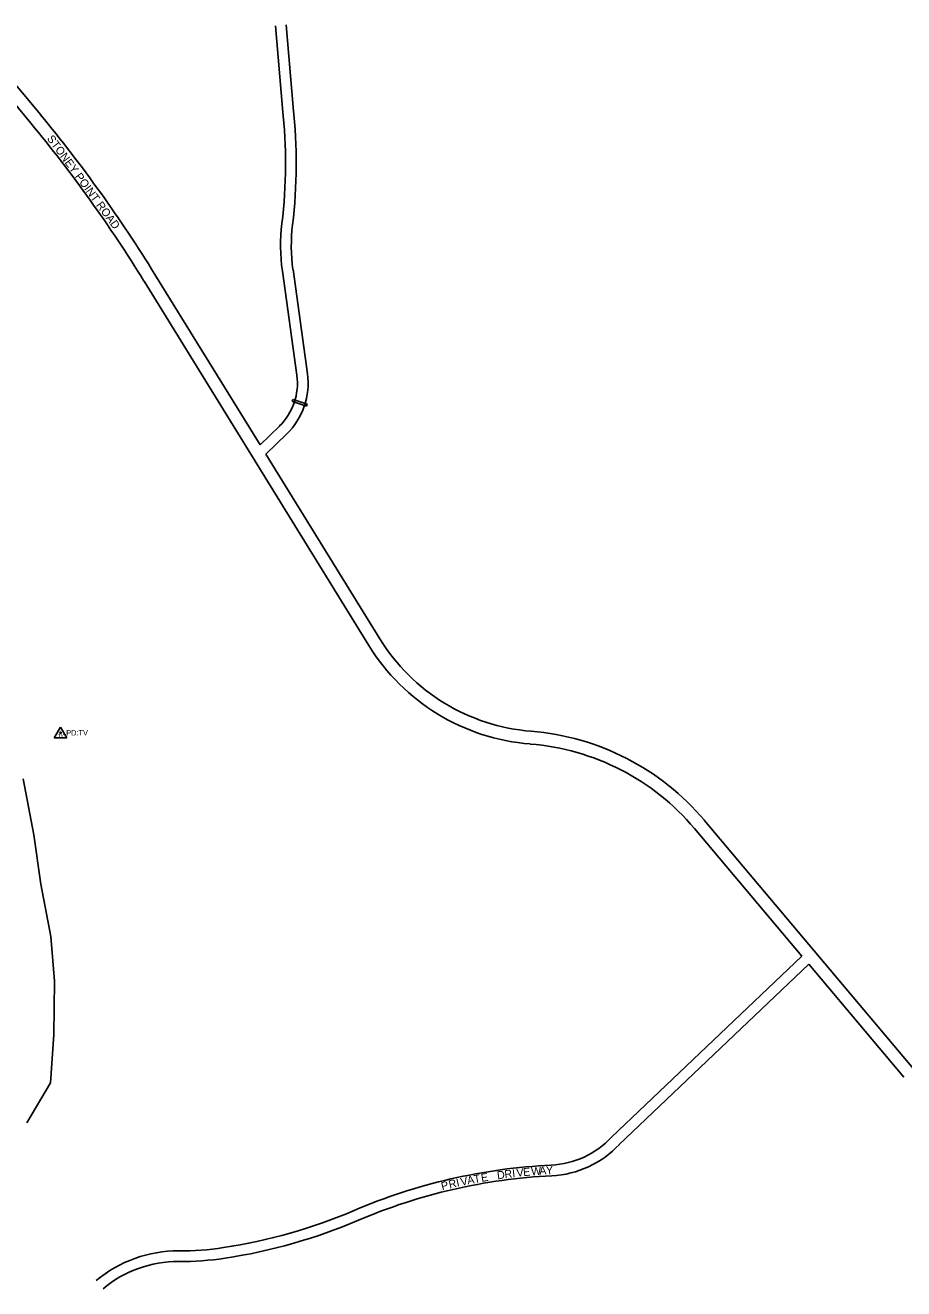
# Model space of a CAD drawing. Extents: x 1574966 to 1597594, y 720505 to 737840.
# Drawn here: x 1578235 to 1579058, y 723543 to 724727 of the extents above; entities that cross this region are included whole.
import ezdxf

# ---------------------------------------------------------------- set-up
doc = ezdxf.new("R2010")
doc.units = 0
for name, color, linetype in [('S_BREAKLINE', 7, 'Continuous'), ('S_EDGE_PAVEMENT', 7, 'Continuous'), ('S_EDGE_PAVEMENT_AERIAL', 7, 'Continuous'), ('S_EDGE_PAVEMENT_AERIAL_TEXT', 7, 'Continuous'), ('S_GATE', 7, 'Continuous'), ('S_GRAVEL_ROAD_AERIAL', 7, 'Continuous'), ('S_SECONDARY_CTL', 7, 'Continuous'), ('S_SECONDARY_CTL_ANNOT', 7, 'Continuous')]:
    doc.layers.add(name, color=color, linetype=linetype)

msp = doc.modelspace()

# ---------------------------------------------------------------- linework, layer by layer
at = {"layer": 'S_BREAKLINE'}
for p, q in [((1578233.1, 724020.5), (1578243.1, 723967.9)), ((1578243.1, 723967.9), (1578249.6, 723921.7)), ((1578249.6, 723921.7), (1578259, 723872.9)), ((1578259, 723872.9), (1578262.4, 723831)), ((1578262.4, 723831), (1578261.7, 723781)), ((1578261.7, 723781), (1578258.7, 723735.6)), ((1578258.7, 723735.6), (1578236.3, 723698.1))]:
    msp.add_line(p, q, dxfattribs=at)
at = {"layer": 'S_EDGE_PAVEMENT'}
for p, q in [((1578870.9, 723981.7), (1579066.9, 723748.6)), ((1578861.8, 723974), (1578962.2, 723854.4)), ((1578968.7, 723846.8), (1579057.7, 723740.9))]:
    msp.add_line(p, q, dxfattribs=at)
at = {"layer": 'S_EDGE_PAVEMENT_AERIAL'}
for p, q in [((1578479.3, 724727.3), (1578485.8, 724650)), ((1578205.3, 724677.2), (1578240.1, 724635.2)), ((1578214.6, 724684.9), (1578249.4, 724642.8)), ((1578485.7, 724497.8), (1578499.2, 724400.3)), ((1578346.2, 724487.1), (1578556.6, 724145.6)), ((1578356.4, 724493.4), (1578454.9, 724333.5)), ((1578489.3, 724398.9), (1578475.8, 724496.5)), ((1578475.8, 724496.5), (1578489.3, 724398.9)), ((1578489.3, 724398.9), (1578475.8, 724496.5)), ((1578475.8, 724496.5), (1578489.3, 724398.9)), ((1578454.9, 724333.5), (1578472.9, 724351)), ((1578472.9, 724351), (1578454.9, 724333.5)), ((1578454.9, 724333.5), (1578472.9, 724351)), ((1578472.9, 724351), (1578454.9, 724333.5)), ((1578479.9, 724343.9), (1578460.3, 724324.7)), ((1578460.3, 724324.7), (1578566.9, 724151.8)), ((1578962.2, 723854.4), (1578784, 723684.7))]:
    msp.add_line(p, q, dxfattribs=at)
for centre, radius, start, end in [((1577227.1, 723797.6), 1326.4, 31.6399, 39.5861), ((1578005.2, 724597), 473.5, 353.2149, 6.2854), ((1578005.2, 724597), 473.5, 353.2149, 6.2854), ((1578005.2, 724597), 473.5, 353.2149, 6.2854), ((1578005.2, 724597), 473.5, 353.2149, 6.2854), ((1578005.2, 724597), 483.5, 353.2149, 6.2854), ((1577227.1, 723797.6), 1314.4, 31.6399, 39.5861), ((1578648.8, 724520.5), 174.7, 173.2149, 187.9025), ((1578648.8, 724520.5), 174.7, 173.2149, 187.9025), ((1578648.8, 724520.5), 174.7, 173.2149, 187.9025), ((1578648.8, 724520.5), 174.7, 173.2149, 187.9025), ((1578648.8, 724520.5), 164.7, 173.2149, 187.9025), ((1578433.7, 724391.2), 56.1, 314.2902, 7.9025), ((1578433.7, 724391.2), 56.1, 314.2902, 7.9025), ((1578433.7, 724391.2), 56.1, 314.2902, 7.9025), ((1578433.7, 724391.2), 56.1, 314.2902, 7.9025), ((1578433.7, 724391.2), 66.1, 314.2902, 7.9025), ((1578723.2, 724248.2), 195.6, 211.6399, 265.5045), ((1578723.2, 724248.2), 183.6, 211.6399, 265.5045), ((1578690.3, 723829.8), 236, 40.0477, 85.5045), ((1578690.3, 723829.8), 224, 40.0477, 85.5045), ((1578723.6, 723741), 82.6, 272.7693, 317.0285), ((1578753.4, 723124.5), 534.6, 92.7693, 113.1637), ((1578344.8, 724079.5), 504.1, 278.641, 293.1637), ((1578377.9, 723459.2), 118.9, 89.581, 130.0381), ((1578380.7, 723843.6), 265.5, 269.581, 278.641)]:
    msp.add_arc(centre, radius, start, end, dxfattribs=at)
at = {"layer": 'S_GATE'}
for p, q in [((1578498.4, 724369.8), (1578485.1, 724374.2)), ((1578485.7, 724376.1), (1578499, 724371.7))]:
    msp.add_line(p, q, dxfattribs=at)
for radius, end in [(54.1, 343.7966), (68.1, 343.3615)]:
    msp.add_arc((1578433.7, 724391.2), radius, 341.6796, end, dxfattribs=at)
at = {"layer": 'S_GRAVEL_ROAD_AERIAL'}
for p, q in [((1578475.8, 724649.1), (1578469.4, 724726.4)), ((1578475.8, 724649.1), (1578469.4, 724726.4)), ((1578489.3, 724398.9), (1578475.8, 724496.5)), ((1578489.3, 724398.9), (1578475.8, 724496.5)), ((1578454.9, 724333.5), (1578472.9, 724351)), ((1578454.9, 724333.5), (1578472.9, 724351)), ((1578790.9, 723677.5), (1578968.7, 723846.8))]:
    msp.add_line(p, q, dxfattribs=at)
for centre, radius, start, end in [((1578005.2, 724597), 473.5, 353.2149, 6.2854), ((1578005.2, 724597), 473.5, 353.2149, 6.2854), ((1578648.8, 724520.5), 174.7, 173.2149, 187.9025), ((1578648.8, 724520.5), 174.7, 173.2149, 187.9025), ((1578433.7, 724391.2), 56.1, 314.2902, 7.9025), ((1578433.7, 724391.2), 56.1, 314.2902, 7.9025), ((1578723.6, 723741), 92.6, 272.7693, 317.0285), ((1578753.4, 723124.5), 524.6, 92.7693, 113.1637), ((1578344.8, 724079.5), 514.1, 278.641, 293.1637), ((1578377.9, 723459.2), 108.9, 89.581, 130.0381), ((1578380.7, 723843.6), 275.5, 269.581, 278.641)]:
    msp.add_arc(centre, radius, start, end, dxfattribs=at)
at = {"layer": 'S_SECONDARY_CTL'}
for p, q in [((1578268, 724068.9), (1578262, 724059)), ((1578268, 724068.9), (1578262, 724059)), ((1578268, 724068.9), (1578262, 724059)), ((1578268, 724068.9), (1578262, 724059)), ((1578268, 724068.9), (1578262, 724059)), ((1578268, 724068.9), (1578262, 724059)), ((1578262, 724059), (1578273.9, 724059)), ((1578262, 724059), (1578273.9, 724059)), ((1578262, 724059), (1578273.9, 724059)), ((1578262, 724059), (1578273.9, 724059)), ((1578262, 724059), (1578273.9, 724059)), ((1578262, 724059), (1578273.9, 724059)), ((1578268, 724068.9), (1578273.9, 724059)), ((1578268, 724068.9), (1578273.9, 724059)), ((1578268, 724068.9), (1578273.9, 724059)), ((1578268, 724068.9), (1578273.9, 724059)), ((1578268, 724068.9), (1578273.9, 724059)), ((1578268, 724068.9), (1578273.9, 724059))]:
    msp.add_line(p, q, dxfattribs=at)
for radius in [0.622, 0.622, 0.622, 0.622, 0.622, 0.622, 0.365, 0.365, 0.365, 0.365, 0.365, 0.365, 0.207, 0.207, 0.207, 0.207, 0.207, 0.207]:
    msp.add_circle((1578268, 724063.7), radius, dxfattribs=at)

# ---------------------------------------------------------------- texts
at = {"layer": 'S_EDGE_PAVEMENT_AERIAL_TEXT'}
for s, rotation, p in [('STONEY POINT ROAD', 306.4815, (1578254.9, 724620.5)), ('W', 4.4515, (1578709, 723648.8)), ('A', 3.6348, (1578716.5, 723649.4)), ('Y', 2.9477, (1578722.8, 723649.8)), ('R', 12.9045, (1578632.4, 723636.6)), ('I', 12.1201, (1578639.4, 723638.2)), ('V', 11.6793, (1578643.4, 723639)), ('A', 11.0051, (1578649.5, 723640.3)), ('T', 10.318, (1578655.7, 723641.5)), ('E', 9.5661, (1578662.4, 723642.7)), ('D', 7.9325, (1578677.3, 723645.1)), ('R', 7.1676, (1578684.2, 723646.1)), ('I', 6.3833, (1578691.4, 723647)), ('V', 5.9425, (1578695.4, 723647.5)), ('E', 5.2683, (1578701.5, 723648.1)), ('P', 13.6888, (1578625.4, 723634.9))]:
    msp.add_text(s, height=7.5, rotation=rotation, dxfattribs=at).set_placement(p)
at = {"layer": 'S_SECONDARY_CTL'}
msp.add_text('TV', height=3, rotation=360, dxfattribs=at).set_placement((1578265.6, 724059.7))
msp.add_text('TV', height=3, rotation=360, dxfattribs=at).set_placement((1578265.6, 724059.7))
msp.add_text('TV', height=3, rotation=360, dxfattribs=at).set_placement((1578265.6, 724059.7))
msp.add_text('TV', height=3, rotation=360, dxfattribs=at).set_placement((1578265.6, 724059.7))
msp.add_text('TV', height=3, rotation=360, dxfattribs=at).set_placement((1578265.6, 724059.7))
msp.add_text('TV', height=3, rotation=360, dxfattribs=at).set_placement((1578265.6, 724059.7))
at = {"layer": 'S_SECONDARY_CTL_ANNOT'}
msp.add_text('PD:TV', height=5, dxfattribs=at).set_placement((1578273.3, 724061.2))

doc.saveas('drawing.dxf')
